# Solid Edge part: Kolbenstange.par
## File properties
Username: bmolnar
Dokumentum tartalom típus: 0
Author: bmolnar
Last saved by: bmolnar
Revision: 82
Sűrűség: 0,000 kg/m^3
Pontosság: 0,990
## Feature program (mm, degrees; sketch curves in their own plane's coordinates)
base feature "unnamed BaseFeature 1"
sketch for "unnamed Protrusion 1" #1 plane through (21, 0.0012, 0) normal (1, 0, 0) x-axis (0, 1, 0)
  circle centre (-0.0012, 0) radius 3.2
sketch for "unnamed Protrusion 1" #2 plane through (21, 0.0012, 0) normal (1, 0, 0) x-axis (0, 1, 0)
  circle centre (-0.0012, 0) radius 8
extrude "unnamed Protrusion 1" add finite 11.1 along -normal
sketch for "Kihúzás_3" plane through (21, 0.0012, 0) normal (1, 0, 0) x-axis (0, 1, 0)
  circle centre (-0.0012, 0) radius 8
extrude "Kihúzás_3" add finite 4.5 along +normal
sketch for "Furat_1" plane through (-21, 0, 0.0012) normal (-1, 0, 0) x-axis (0, 0, -1)
  hole centre (0.0012, 0) bore radius 1.621
hole "Furat_1" nominal diameter 4 finite  ThreadDepth = 9 mm; StartChamferOffset = 0.3 mm; StartChamferAngle = 45 deg; VBottomAngle = 118 deg
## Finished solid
Body 1: solid body, 18 faces, 24 edges, 8 vertices.
  Faces by surface: plane 8, cylinder 5, cone 3, torus 2
  Edges by curve: circle 14, line 6, curve on surface 2, ellipse 2
Bounding box of the edges (mm; curved faces can reach further): 48.500 x 16.000 x 16.000, from (-23, -8, -8) to (25.5, 8, 8).
Cylindrical faces by radius (mm): R1.621 x2, R2.125 x1, R4 x1, R8 x1
Conical faces (half-angle, radius in mm at the cone's reference point): 45 deg R1.921 x1, 45 deg R2.225 x1, 59 deg R1.621 x1
Toroidal faces (ring radius, tube radius in mm): R1.925 r0.2 x1, R2.7 r1.3 x1
Planar faces by outward normal: +x 1, +z 1, -x 3, -z 1, oblique 2
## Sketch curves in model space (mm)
circle centre (21, 0, 0) radius 8
circle centre (21, 0, 0) radius 3.2
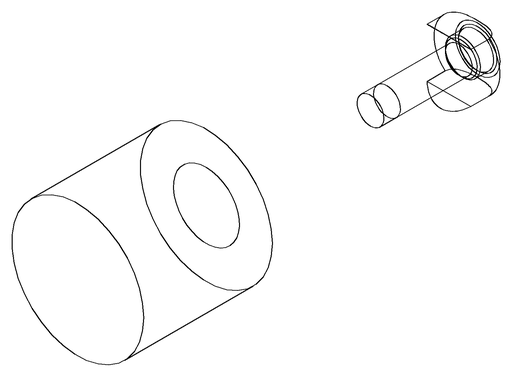
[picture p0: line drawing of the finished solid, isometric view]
